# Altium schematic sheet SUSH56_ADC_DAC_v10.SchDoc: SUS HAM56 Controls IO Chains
size C; Engineer: L. Sanchez; Organization: LIGO Laboratory; Address1: California Institute of Technology; Address2: Massachusetts Institute of Technology; DocumentNumber: D1002740; Revision: v10; SheetNumber: 5; SheetTotal: 8
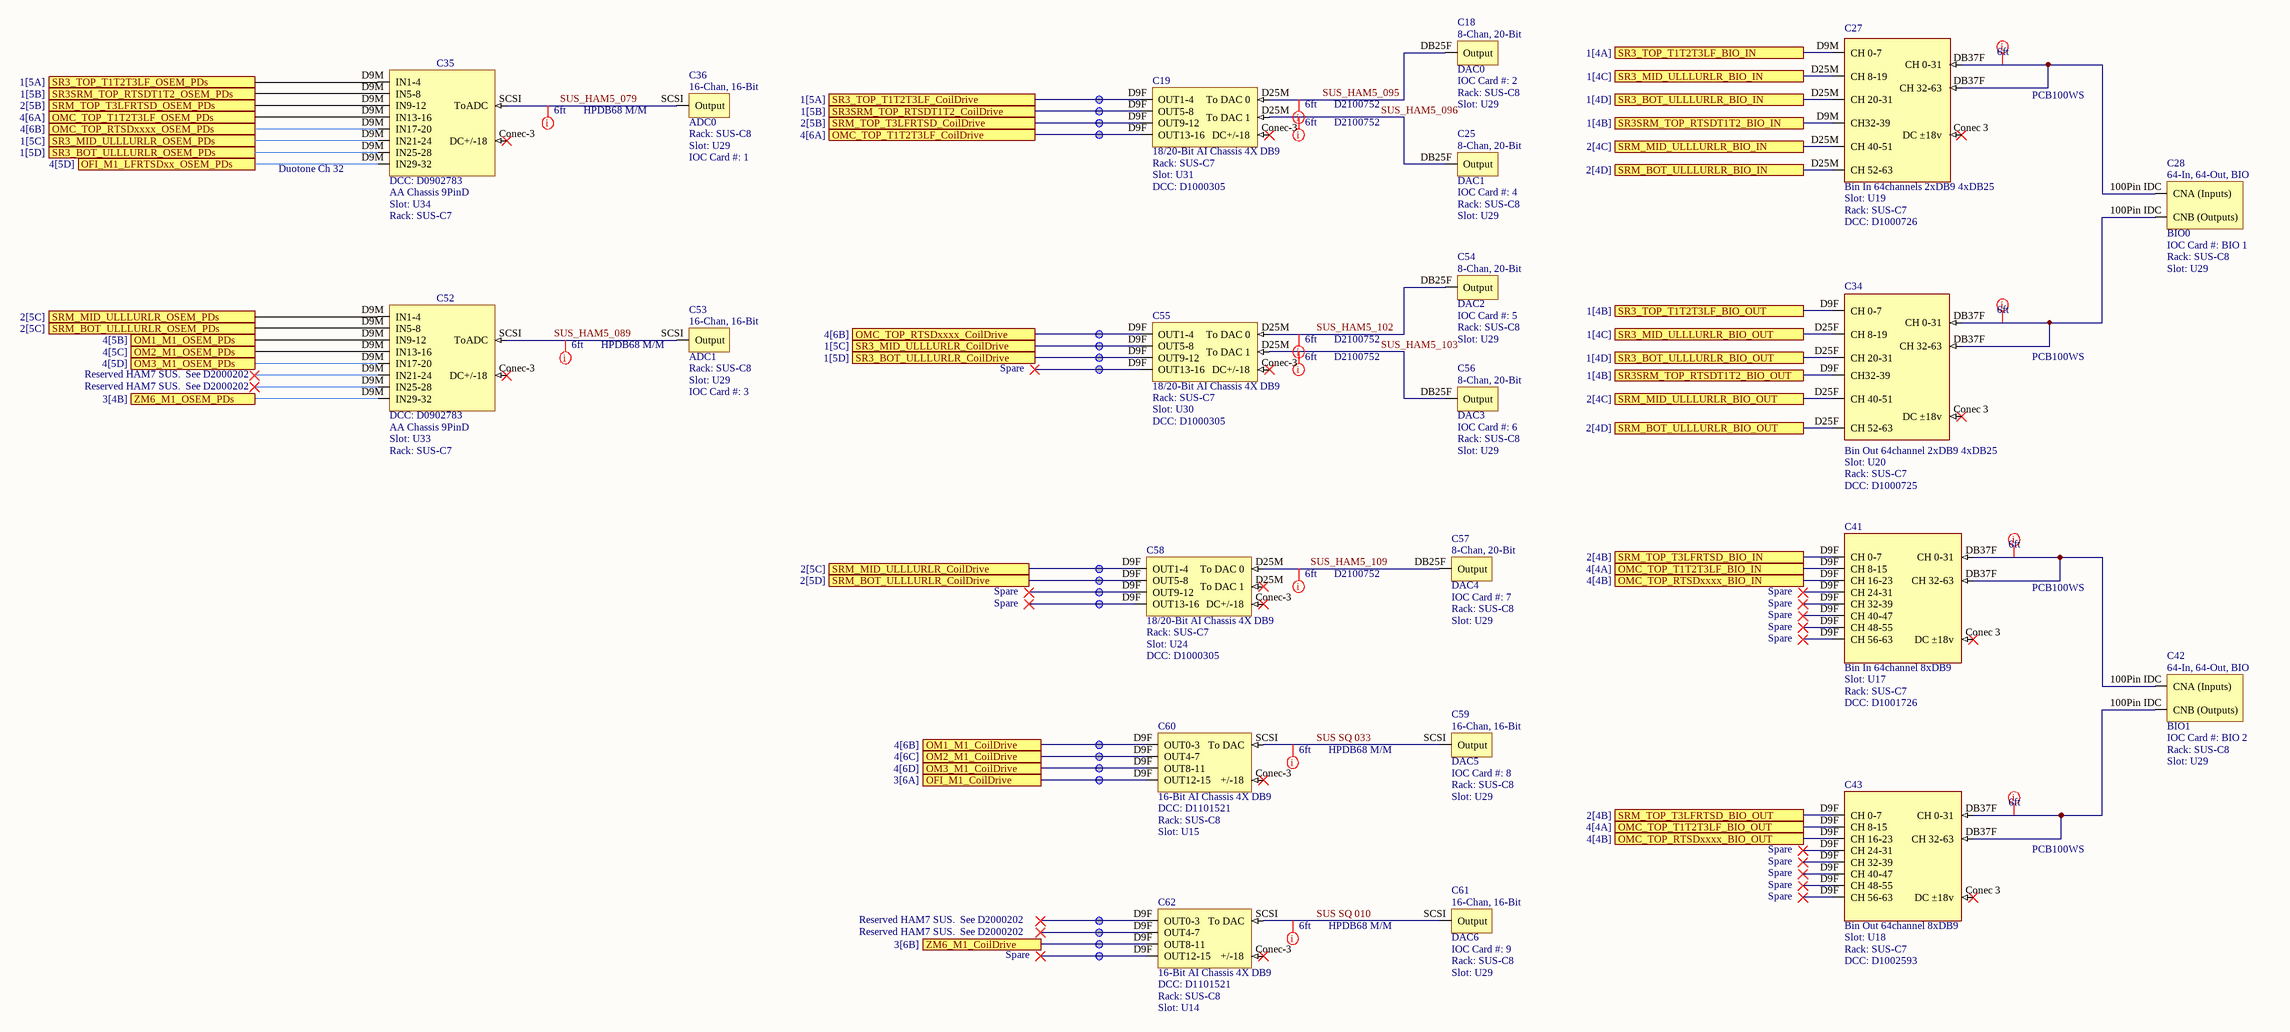
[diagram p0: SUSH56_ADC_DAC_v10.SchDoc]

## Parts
C18  DAC0  IOC Card #: 2  Rack: SUS-C8  Slot: U29
C19  18/20-Bit AI Chassis 4X DB9  Rack: SUS-C7  Slot: U31  DCC: D1000305
C25  DAC1  IOC Card #: 4  Rack: SUS-C8  Slot: U29
C27  Bin In 64channels 2xDB9 4xDB25  Slot: U19  Rack: SUS-C7  DCC: D1000726
C28  BIO0  IOC Card #: BIO 1  Rack: SUS-C8  Slot: U29
C34  Bin Out 64channel 2xDB9 4xDB25  Slot: U20  Rack: SUS-C7  DCC: D1000725
C35  AA Chassis 9PinD  DCC: D0902783  Rack: SUS-C7  Slot: U34
C36  ADC0  Rack: SUS-C8  Slot: U29  IOC Card #: 1
C41  Bin In 64channel 8xDB9  Slot: U17  Rack: SUS-C7  DCC: D1001726
C42  BIO1  IOC Card #: BIO 2  Rack: SUS-C8  Slot: U29
C43  Bin Out 64channel 8xDB9  Slot: U18  Rack: SUS-C7  DCC: D1002593
C52  AA Chassis 9PinD  DCC: D0902783  Rack: SUS-C7  Slot: U33
C53  ADC1  Rack: SUS-C8  Slot: U29  IOC Card #: 3
C54  DAC2  IOC Card #: 5  Rack: SUS-C8  Slot: U29
C55  18/20-Bit AI Chassis 4X DB9  Rack: SUS-C7  Slot: U30  DCC: D1000305
C56  DAC3  IOC Card #: 6  Rack: SUS-C8  Slot: U29
C57  DAC4  IOC Card #: 7  Rack: SUS-C8  Slot: U29
C58  18/20-Bit AI Chassis 4X DB9  Rack: SUS-C7  Slot: U24  DCC: D1000305
C59  DAC5  IOC Card #: 8  Rack: SUS-C8  Slot: U29
C60  16-Bit AI Chassis 4X DB9  DCC: D1101521  Rack: SUS-C8  Slot: U15
C61  DAC6  IOC Card #: 9  Rack: SUS-C8  Slot: U29
C62  16-Bit AI Chassis 4X DB9  DCC: D1101521  Rack: SUS-C8  Slot: U14

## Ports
OFI_M1_CoilDrive (see 3[6A]), OFI_M1_LFRTSDxx_OSEM_PDs (see 4[5D]), OM1_M1_CoilDrive (see 4[6B]), OM1_M1_OSEM_PDs (see 4[5B]), OM2_M1_CoilDrive (see 4[6C]), OM2_M1_OSEM_PDs (see 4[5C]), OM3_M1_CoilDrive (see 4[6D]), OM3_M1_OSEM_PDs (see 4[5D]), OMC_TOP_RTSDxxxx_BIO_IN (see 4[4B]), OMC_TOP_RTSDxxxx_BIO_OUT (see 4[4B]), OMC_TOP_RTSDxxxx_CoilDrive (see 4[6B]), OMC_TOP_RTSDxxxx_OSEM_PDs (see 4[6B]), OMC_TOP_T1T2T3LF_BIO_IN (see 4[4A]), OMC_TOP_T1T2T3LF_BIO_OUT (see 4[4A]), OMC_TOP_T1T2T3LF_CoilDrive (see 4[6A]), OMC_TOP_T1T2T3LF_OSEM_PDs (see 4[6A]), SR3_BOT_ULLLURLR_BIO_IN (see 1[4D]), SR3_BOT_ULLLURLR_BIO_OUT (see 1[4D]), SR3_BOT_ULLLURLR_CoilDrive (see 1[5D]), SR3_BOT_ULLLURLR_OSEM_PDs (see 1[5D]), SR3_MID_ULLLURLR_BIO_IN (see 1[4C]), SR3_MID_ULLLURLR_BIO_OUT (see 1[4C]), SR3_MID_ULLLURLR_CoilDrive (see 1[5C]), SR3_MID_ULLLURLR_OSEM_PDs (see 1[5C]), SR3_TOP_T1T2T3LF_BIO_IN (see 1[4A]), SR3_TOP_T1T2T3LF_BIO_OUT (see 1[4B]), SR3_TOP_T1T2T3LF_CoilDrive (see 1[5A]), SR3_TOP_T1T2T3LF_OSEM_PDs (see 1[5A]), SR3SRM_TOP_RTSDT1T2_BIO_IN (see 1[4B]), SR3SRM_TOP_RTSDT1T2_BIO_OUT (see 1[4B]), SR3SRM_TOP_RTSDT1T2_CoilDrive (see 1[5B]), SR3SRM_TOP_RTSDT1T2_OSEM_PDs (see 1[5B]), SRM_BOT_ULLLURLR_BIO_IN (see 2[4D]), SRM_BOT_ULLLURLR_BIO_OUT (see 2[4D]), SRM_BOT_ULLLURLR_CoilDrive (see 2[5D]), SRM_BOT_ULLLURLR_OSEM_PDs (see 2[5C]), SRM_MID_ULLLURLR_BIO_IN (see 2[4C]), SRM_MID_ULLLURLR_BIO_OUT (see 2[4C]), SRM_MID_ULLLURLR_CoilDrive (see 2[5C]), SRM_MID_ULLLURLR_OSEM_PDs (see 2[5C]), SRM_TOP_T3LFRTSD_BIO_IN (see 2[4B]), SRM_TOP_T3LFRTSD_BIO_OUT (see 2[4B]), SRM_TOP_T3LFRTSD_CoilDrive (see 2[5B]), SRM_TOP_T3LFRTSD_OSEM_PDs (see 2[5B]), ZM6_M1_CoilDrive (see 3[6B]), ZM6_M1_OSEM_PDs (see 3[4B])

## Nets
OFI_M1_CoilDrive: C60.D9F(OUT12-15) ; port OFI_M1_CoilDrive
OFI_M1_LFRTSDxx_OSEM_PDs: C35.D9M(IN29-32) ; port OFI_M1_LFRTSDxx_OSEM_PDs
OM1_M1_CoilDrive: C60.D9F(OUT0-3) ; port OM1_M1_CoilDrive
OM1_M1_OSEM_PDs: C52.D9M(IN9-12) ; port OM1_M1_OSEM_PDs
OM2_M1_CoilDrive: C60.D9F(OUT4-7) ; port OM2_M1_CoilDrive
OM2_M1_OSEM_PDs: C52.D9M(IN13-16) ; port OM2_M1_OSEM_PDs
OM3_M1_CoilDrive: C60.D9F(OUT8-11) ; port OM3_M1_CoilDrive
OM3_M1_OSEM_PDs: C52.D9M(IN17-20) ; port OM3_M1_OSEM_PDs
OMC_TOP_RTSDxxxx_BIO_IN: C41.D9F(CH_16-23) ; port OMC_TOP_RTSDxxxx_BIO_IN
OMC_TOP_RTSDxxxx_BIO_OUT: C43.D9F(CH_16-23) ; port OMC_TOP_RTSDxxxx_BIO_OUT
OMC_TOP_RTSDxxxx_CoilDrive: C55.D9F(OUT1-4) ; port OMC_TOP_RTSDxxxx_CoilDrive
OMC_TOP_RTSDxxxx_OSEM_PDs: C35.D9M(IN17-20) ; port OMC_TOP_RTSDxxxx_OSEM_PDs
OMC_TOP_T1T2T3LF_BIO_IN: C41.D9F(CH_8-15) ; port OMC_TOP_T1T2T3LF_BIO_IN
OMC_TOP_T1T2T3LF_BIO_OUT: C43.D9F(CH_8-15) ; port OMC_TOP_T1T2T3LF_BIO_OUT
OMC_TOP_T1T2T3LF_CoilDrive: C19.D9F(OUT13-16) ; port OMC_TOP_T1T2T3LF_CoilDrive
OMC_TOP_T1T2T3LF_OSEM_PDs: C35.D9M(IN13-16) ; port OMC_TOP_T1T2T3LF_OSEM_PDs
SR3_BOT_ULLLURLR_BIO_IN: C27.D25M(CH_20-31) ; port SR3_BOT_ULLLURLR_BIO_IN
SR3_BOT_ULLLURLR_BIO_OUT: C34.D25F(CH_20-31) ; port SR3_BOT_ULLLURLR_BIO_OUT
SR3_BOT_ULLLURLR_CoilDrive: C55.D9F(OUT9-12) ; port SR3_BOT_ULLLURLR_CoilDrive
SR3_BOT_ULLLURLR_OSEM_PDs: C35.D9M(IN25-28) ; port SR3_BOT_ULLLURLR_OSEM_PDs
SR3_MID_ULLLURLR_BIO_IN: C27.D25M(CH_8-19) ; port SR3_MID_ULLLURLR_BIO_IN
SR3_MID_ULLLURLR_BIO_OUT: C34.D25F(CH_8-19) ; port SR3_MID_ULLLURLR_BIO_OUT
SR3_MID_ULLLURLR_CoilDrive: C55.D9F(OUT5-8) ; port SR3_MID_ULLLURLR_CoilDrive
SR3_MID_ULLLURLR_OSEM_PDs: C35.D9M(IN21-24) ; port SR3_MID_ULLLURLR_OSEM_PDs
SR3_TOP_T1T2T3LF_BIO_IN: C27.D9M(CH_0-7) ; port SR3_TOP_T1T2T3LF_BIO_IN
SR3_TOP_T1T2T3LF_BIO_OUT: C34.D9F(CH_0-7) ; port SR3_TOP_T1T2T3LF_BIO_OUT
SR3_TOP_T1T2T3LF_CoilDrive: C19.D9F(OUT1-4) ; port SR3_TOP_T1T2T3LF_CoilDrive
SR3_TOP_T1T2T3LF_OSEM_PDs: C35.D9M(IN1-4) ; port SR3_TOP_T1T2T3LF_OSEM_PDs
SR3SRM_TOP_RTSDT1T2_BIO_IN: C27.D9M(CH32-39) ; port SR3SRM_TOP_RTSDT1T2_BIO_IN
SR3SRM_TOP_RTSDT1T2_BIO_OUT: C34.D9F(CH32-39) ; port SR3SRM_TOP_RTSDT1T2_BIO_OUT
SR3SRM_TOP_RTSDT1T2_CoilDrive: C19.D9F(OUT5-8) ; port SR3SRM_TOP_RTSDT1T2_CoilDrive
SR3SRM_TOP_RTSDT1T2_OSEM_PDs: C35.D9M(IN5-8) ; port SR3SRM_TOP_RTSDT1T2_OSEM_PDs
SRM_BOT_ULLLURLR_BIO_IN: C27.D25M(CH_52-63) ; port SRM_BOT_ULLLURLR_BIO_IN
SRM_BOT_ULLLURLR_BIO_OUT: C34.D25F(CH_52-63) ; port SRM_BOT_ULLLURLR_BIO_OUT
SRM_BOT_ULLLURLR_CoilDrive: C58.D9F(OUT5-8) ; port SRM_BOT_ULLLURLR_CoilDrive
SRM_BOT_ULLLURLR_OSEM_PDs: C52.D9M(IN5-8) ; port SRM_BOT_ULLLURLR_OSEM_PDs
SRM_MID_ULLLURLR_BIO_IN: C27.D25M(CH_40-51) ; port SRM_MID_ULLLURLR_BIO_IN
SRM_MID_ULLLURLR_BIO_OUT: C34.D25F(CH_40-51) ; port SRM_MID_ULLLURLR_BIO_OUT
SRM_MID_ULLLURLR_CoilDrive: C58.D9F(OUT1-4) ; port SRM_MID_ULLLURLR_CoilDrive
SRM_MID_ULLLURLR_OSEM_PDs: C52.D9M(IN1-4) ; port SRM_MID_ULLLURLR_OSEM_PDs
SRM_TOP_T3LFRTSD_BIO_IN: C41.D9F(CH_0-7) ; port SRM_TOP_T3LFRTSD_BIO_IN
SRM_TOP_T3LFRTSD_BIO_OUT: C43.D9F(CH_0-7) ; port SRM_TOP_T3LFRTSD_BIO_OUT
SRM_TOP_T3LFRTSD_CoilDrive: C19.D9F(OUT9-12) ; port SRM_TOP_T3LFRTSD_CoilDrive
SRM_TOP_T3LFRTSD_OSEM_PDs: C35.D9M(IN9-12) ; port SRM_TOP_T3LFRTSD_OSEM_PDs
SUS SQ 010: C61.SCSI(Output) C62.SCSI(To_DAC)
SUS SQ 033: C59.SCSI(Output) C60.SCSI(To_DAC)
SUS_HAM5_079: C35.SCSI(ToADC) C36.SCSI(Output)
SUS_HAM5_089: C52.SCSI(ToADC) C53.SCSI(Output)
SUS_HAM5_095: C18.DB25F(Output) C19.D25M(To_DAC_0)
SUS_HAM5_096: C19.D25M(To_DAC_1) C25.DB25F(Output)
SUS_HAM5_102: C54.DB25F(Output) C55.D25M(To_DAC_0)
SUS_HAM5_103: C55.D25M(To_DAC_1) C56.DB25F(Output)
SUS_HAM5_109: C57.DB25F(Output) C58.D25M(To_DAC_0)
ZM6_M1_CoilDrive: C62.D9F(OUT0-3) ; port ZM6_M1_CoilDrive
ZM6_M1_OSEM_PDs: C52.D9M(IN29-32) ; port ZM6_M1_OSEM_PDs
NetC27_DB37F: C27.DB37F(CH_0-31) C28.100Pin_IDC(CNA_(Inputs))
NetC28_100Pin IDC: C28.100Pin_IDC(CNB_(Outputs)) C34.DB37F(CH_0-31)
NetC41_DB37F: C41.DB37F(CH_0-31) C42.100Pin_IDC(CNA_(Inputs))
NetC42_100Pin IDC: C42.100Pin_IDC(CNB_(Outputs)) C43.DB37F(CH_0-31)

Not connected (* = marked no-connect by the designer): C19 Conec-3(DC+/-18)*; C27 Conec 3(DC_±18v)*; C34 Conec 3(DC_±18v)*; C35 Conec-3(DC+/-18)*; C41 Conec 3(DC_±18v)*; C43 Conec 3(DC_±18v)*; C52 Conec-3(DC+/-18)*; C55 Conec-3(DC+/-18)*; C58 Conec-3(DC+/-18)*; C60 Conec-3(+/-18)*; C62 Conec-3(+/-18)*

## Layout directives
Length: 6ft; DCC: Dxxxxxxx: NetC27_DB37F, NetC28_100Pin IDC, NetC41_DB37F, NetC42_100Pin IDC
Length: 6ft; DCC: HPDB68 M/M: SUS SQ 010, SUS SQ 033, SUS_HAM5_079, SUS_HAM5_089
Length: 6ft; DCC: D2100752: SUS_HAM5_095, SUS_HAM5_096, SUS_HAM5_102, SUS_HAM5_103, SUS_HAM5_109

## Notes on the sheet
- PCB100WS
- (near C35) Duotone Ch 32
- Reserved HAM7 SUS.  See D2000202
- Spare

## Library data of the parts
C18 C25 C54 C56 C57 = DAC-20: 8 Chan, 20 Bit DAC
C19 C55 C58 = AI_9Pin_18_20_Bit: System: SUS; Serial: Sxxxxxxx
C27 = Bin_In_64ch_2xDB9_4xDB25: Serial: Sxxxxxxx; System: SUS
C28 C42 = Binary IO: 128 Chan, Contec DIO-6464L-PE
C34 = Bin_Out_64ch_2xDB9_4xDB25: Serial: Sxxxxxxx; System: SUS
C35 C52 = AA_9pinAll: ISC AA Chassis 9PinD; Serial: Sxxxxxxx
C36 C53 = ADC-16: 16 Chan, 16 Bit ADC
C41 = Bin In 64cha_8xDB9: Serial: Sxxxxxxx; System: SUS
C43 = Bin Out 64cha_8xDB9: Serial: Sxxxxxxx; System: SUS
C59 C61 = DAC-16: 16 Chan, 16 Bit DAC
C60 C62 = AI_9pin_16_bit: AI Chassis 4X DB9 16-bit; Serial: Sxxxxxxx; System: ISC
